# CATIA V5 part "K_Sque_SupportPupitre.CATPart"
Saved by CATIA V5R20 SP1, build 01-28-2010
Part number: squelette_support_pupitre
Publications: "Point.1", "Point.2", "Droite.1", "Plan.1", "Droite.2", "Droite.3", "Point.3", "Point.4", "Point.5", "Point.6", "Droite.4", "Droite.5", "Droite.6"
Bounding box of the stored display mesh (mm): x -7 to 0, y -4 to 20, z -30 to 65
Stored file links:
  G:\Khaled_CFAO_2011\ST2M\ST2M_GR2\gcausse\Khaled\CAD_ThinkMotion\K_Sque_SupportPupitre.CATPart
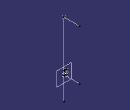
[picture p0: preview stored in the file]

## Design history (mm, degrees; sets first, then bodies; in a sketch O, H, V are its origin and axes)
Set1
  Point1: (0, 0, 0)
  Point2: (0, 0, 65)
  Line1: type PtPt, FirstPoint Point2, SecondPoint Point1, End 30
  Plane1: type Offset, RefPlane zx-plane, Offset 0
  Line2: type PtDir, RefPoint Point1, Direction Plane1, Start 0, End 20
  Line3: type PtDir, RefPoint Point2, Direction Plane1, Start 0, End 20
  Point3: (-5, -4, 0)
  Point4: (-7, -4, 0)
  Point5: (-7, -4, -5)
  Point6: (-5, -4, -5)
  Line4: type PtPt, FirstPoint Point3, SecondPoint Point4
  Line5: type PtPt, FirstPoint Point6, SecondPoint Point5
  Line6: type PtPt, FirstPoint Point4, SecondPoint Point5
Body1 (main body)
